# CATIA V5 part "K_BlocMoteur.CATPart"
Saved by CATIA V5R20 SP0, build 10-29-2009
Part number: Bloc_moteur
Publications: "Point.3"
Bounding box of the stored display mesh (mm): x 100 to 450, y -249.718 to -34.888, z -107.415 to 107.415
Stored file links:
  G:\Khaled_CFAO_2011\ST2M\ST2M_GR2\jcoetard\Khaled\CAD_CATIA\K_BlocMoteur.CATPart
  J:\Thinkmotion\Thinkmotion_COETARD\Maquette_catia\Maquette_catia_R20_Licence_education\jcharlescoetard.CATPRODUCT\Assemblage_Pince_Prehension_Mors_Paralleles.CATProduct
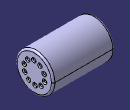
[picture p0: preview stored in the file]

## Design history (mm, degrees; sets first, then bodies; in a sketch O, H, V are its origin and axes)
Set1
  Point1 "Point_centre_écrou": linked copy from another document
  Plane1 "Plan_bloc_moteur": linked copy from another document
  Point2 "Point_centre_écrou": linked copy from another document
Set2 "Set géométrique"
  Point3: type OnPlane, Support start face of Pad1, H 200, V 15, Direction (0, -1, 0)
Body1 (main body)
  Sketch1 on Plane1, origin (100, 0, 0), H (0, 1, 0), V (0, 0, 1)
    circle A1 centre (-142.303, 0) radius 107.4151
    point P1 (-142.303, 0)
    reference projected point E1 (-142.303, 0) from Point1
    coincidence: P1 E1
  Pad1: profile Sketch1, direction (1, 0, 0), length 350
  Sketch2 on start face of Pad1, origin (100, -142.303, 0), H (0, 1, 0), V (0, 0, -1)
    point P1 (0, 0)
    reference projected point E1 (0, 0) from Point2
    coincidence: E1 P1
  Hole1: placed by Sketch2, at (100, -142.303, 0) direction (1, 0, 0), diameter 30, depth 100
  Sketch3 on start face of Pad1, origin (100, -200, 15), H (0, 1, 0), V (0, 0, -1)
    point P1 (0, 0)
    reference projected point E1 (0, 0) from Point3
    coincidence: E1 P1
  Hole2: placed by Sketch3, at (100, -200, 15) direction (1, 0, 0), diameter 15, depth 400
  CircPattern1: of Hole2, instances 10, angular step 36, axis from face of Pad1 from Sketch1.A1
  Fillet1: radius 10, on start face of Pad1; edge [face of Pad1 from Sketch1.A1 | end face of Pad1]
  Fillet2: radius 5, on end face of Pad1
